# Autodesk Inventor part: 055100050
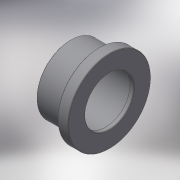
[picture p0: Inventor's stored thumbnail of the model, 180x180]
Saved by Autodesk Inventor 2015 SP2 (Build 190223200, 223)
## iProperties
Created: 2017-10
Part Number: 055100050
Material: Generic
Description: PLASSON FLANGE FLAT AD.-CEM 50
Document SubType Name: Modeling
Designer: KIM
Mass: 43.7767 g
Surface Area: 170.97 cm^2
Volume: 43.7767 cm^3
Density: 1 g/cm^3
Appearance: Default
Author: KIM
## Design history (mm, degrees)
derived "055100.ipt"
feature "Solid1::055100.ipt"
tag "TaggingFeature1"
body "Solid1"
other parameters: "d0" = 34, "d1" = 61, "d3" = 45, "d4" = 8, "d5" = 31, "d6" = 73, "d8" = 0.5, "E_" = 61, "E_1" = 73, "l_" = 31, "B_" = 8, "H_" = 34
